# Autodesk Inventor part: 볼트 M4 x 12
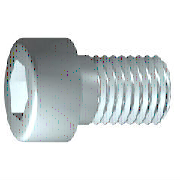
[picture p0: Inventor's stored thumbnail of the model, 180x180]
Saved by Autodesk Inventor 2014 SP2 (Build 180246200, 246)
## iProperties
IsCustomPart: 0
Created: 2012-02
Part Number: 볼트 M4 x 12
Material: 스테인리스강
Description: 6각 소켓 머리 캡 나사
Document SubType Name: Modeling
Standard: ISO 4762
Designer: mduedu
Standard Revision: Fourth edition 2004-03-01
Standards Organization: ISO
Language: ko-KR
Size Designation: M4 x 12
Categories: <MemberInstance><Categories><Category DisplayName="조임쇠" InternalName="e4da775c-781d-43d5-af7c-5136215cf5a6" Mnemonic="FSTN"><Category DisplayName="볼트" InternalN
Density: 8.08 g/cm^3
Appearance: 기본값
Author: mduedu
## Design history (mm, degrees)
sketch "스케치1"
  geometry: L1 (-1, 0)-(12, 0); L2 (12, 0)-(12, 2); L3 (12, 2)-(1.75, 2); L4 (1.75, 2)-(1.32, 2); L5 (1.32, 2)-(0, 2); L6 (0, 2)-(0, 3.5); L7 (0, 3.5)-(-4, 3.5); L8 (-4, 3.5)-(-4, 1.732); L9 (-4, 1.732)-(-2, 1.732); L10 (-2, 1.732)-(-1, 0); L11 (-7.2, 0)-(15.2, 0) reference; L12 (0, -0.7)-(0, 4.2) reference; L13 (1.75, 2)-(0, 2)
  constraints: 22 end point, 6 parallel, 2 collinear, 2 perpendicular, 1 horizontal, 1 point on line
  dimensions: "d1" = 10.25 distance from line of L3.end L2 (= GEL); "d2" = 0.42952 distance of L4.end L3.end (computed from GAL); "d3" = 4 distance between parallel lines of L8 L6 (= KOH); "d4" = 2 distance of L8.end L9.end (= INTI); "d5" = 60 deg angle of L10 L1; "d6" = 4 diameter of L3 L1 (= GD); "d7" = 4 diameter of L5 L1 (= BDM); "d8" = 3.4641 diameter of L9 L1 (= 1.1547 x SW); "d9" = 7 diameter of L7 L1 (= KOD); "d26" = 12 distance between parallel lines of L12 L2 (= NLG)
revolve "본체" sketch "스케치1" stored, may be unused: angle "d10" = 90 deg
sketch "스케치2"
  geometry: L1 (0, -4.9)-(0, 4.9) reference; L2 (-4.9, 0)-(4.9, 0) reference; L3 (1.732, 0)-(0.866, -1.5); L4 (0.866, -1.5)-(-0.866, -1.5); L5 (-0.866, -1.5)-(-1.732, 0); L6 (-1.732, 0)-(-0.866, 1.5); L7 (-0.866, 1.5)-(0.866, 1.5); L8 (0.866, 1.5)-(1.732, 0); 2 further points
  constraints: 12 end point, 1 coincident, 1 horizontal alignment, 1 point on line, 12 other
extrude "슬롯" join sketch "스케치2" stored distance "d11" = 10; taper "d12" = 0 deg
workplane "Work Plane1"
fillet "Fillet2" dims "d30" = 0.1 (= R)
body "Solid1"
fillet "모깎기1" dims "d17" = 0.4 (= RR)
feature "스레드" dims "d13" = 10.25 (= GEL), "d14" = 0
chamfer "모따기1" distance "d15" = 0.42941 (= -0.5 x SPD + 0.5 x GD); stored, may be unused: second distance "d16" = 0.42941 (= GUL), angle "d27" = 45 deg
other parameters: "GD" = 4 [user parameter; used in 2 equation terms], "NLG" = 12 [user parameter; used in 1 equation term], "GEL" = 10.25 [user parameter; used in 2 equation terms], "KOD" = 7 [user parameter; used in 1 equation term], "KOH" = 4 [user parameter; used in 1 equation term], "INTI" = 2 [user parameter; used in 1 equation term], "GAL" = 0.42941 (= 0.61345 x PTC) [user parameter; used in 1 equation term], "GUL" = 0.42941 (= 0.61345 x PTC) [user parameter; used in 1 equation term], "BDM" = 4 (= NND) [user parameter; used in 1 equation term], "SW" = 3 [user parameter; used in 2 equation terms], "RR" = 0.4 [user parameter; used in 1 equation term], "SPD" = 3.14117 (= NND - 1.2269 x PTC) [user parameter; used in 1 equation term], "d19" = 0, "d28" = 0, "d29" = 0, "R" = 0.1 [user parameter; used in 1 equation term], "TOA" = 30 deg [user parameter], "GD1" = 3.14117 (= THREADDIA - 1.2269 x PTC) [user parameter], "THREADDIA" = 4 [user parameter; used in 1 equation term], "FAWI" = 45 deg [user parameter], "TPU" = 14.28571 (computed from PTC) [user parameter], "PTC" = 0.7 [user parameter; used in 5 equation terms], "NND" = 4 [user parameter; used in 2 equation terms], "E0" = 3.465 (= 1.155 x SW) [user parameter]
